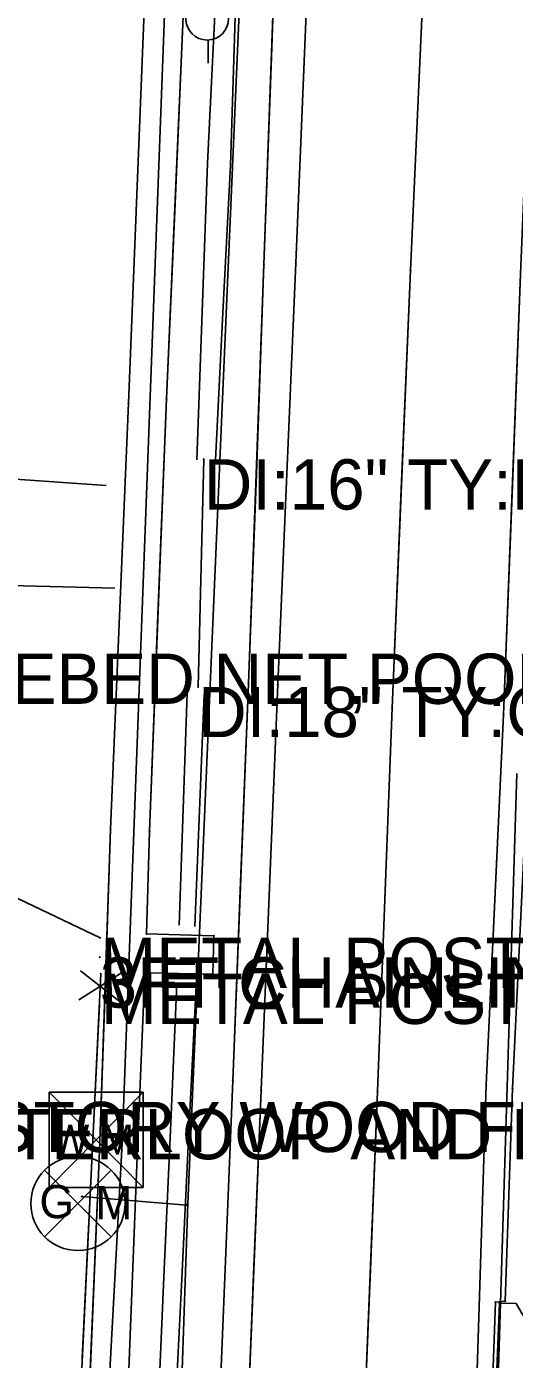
# Model space of a CAD drawing. Extents: x -99999 to 591807, y -99999 to 347168.
# Drawn here: x 591214 to 591262.4, y 320596.6 to 320729.1 of the extents above; entities that cross this region are included whole.
import ezdxf

# ---------------------------------------------------------------- set-up
doc = ezdxf.new("R2010")
doc.units = 0
for name, color, linetype in [('S_DITCHLINE', 7, 'Continuous'), ('S_DRG_PT_SYM', 7, 'Continuous'), ('S_DRIVEWAY', 7, 'Continuous'), ('S_EDGE_PAVEMENT', 7, 'Continuous'), ('S_FENCE', 7, 'Continuous'), ('S_FENCE_ANNOT', 7, 'Continuous'), ('S_GAS_UTILITIES', 7, 'Continuous'), ('S_GATE_ANNOT', 7, 'Continuous'), ('S_MISC_STRUCTURES_ANNOT', 7, 'Continuous'), ('S_MSC_PT_SYM', 7, 'Continuous'), ('S_PAVEMENT_CROWN', 7, 'Continuous'), ('S_RDW_PT_SYM', 7, 'Continuous'), ('S_SHOULDER', 7, 'Continuous'), ('S_SIDE_DRAIN', 7, 'Continuous'), ('S_SIDE_DRAIN_ANNOT', 7, 'Continuous'), ('S_SIDEWALK', 7, 'Continuous'), ('S_SURVEY_TEXT_ANNOT', 7, 'Continuous'), ('S_UTILITY_POLE', 7, 'Continuous'), ('S_UTL_PT_SYM', 7, 'Continuous'), ('S_WATER_UTILITIES', 7, 'Continuous')]:
    doc.layers.add(name, color=color, linetype=linetype)

msp = doc.modelspace()

# ---------------------------------------------------------------- linework, layer by layer
at = {"layer": 'S_DITCHLINE'}
for points in [[(591230.88, 320686.04), (591231.41, 320700.78), (591231.95, 320715.52), (591232.83, 320733.77)], [(591232.75, 320686), (591233.48, 320700.66), (591234.22, 320715.33), (591234.8, 320733.31)], [(591229.15, 320639.76), (591229.93, 320662.82)], [(591230.69, 320639.61), (591231.62, 320662.74)], [(591226.33, 320575.53), (591226.98, 320590.14), (591227.62, 320604.75), (591228.27, 320619.36), (591228.91, 320633.96)], [(591227.95, 320575.42), (591228.67, 320590), (591229.39, 320604.57), (591230.1, 320619.15), (591230.82, 320633.72)]]:
    msp.add_lwpolyline(points, dxfattribs=at)
at = {"layer": 'S_DRG_PT_SYM'}
for points in [[(591231.57, 320686.1), (591231.57, 320686.15), (591231.57, 320686.1), (591231.52, 320686.1), (591231.57, 320686.1), (591231.57, 320686.05), (591231.57, 320686.1), (591231.62, 320686.1)], [(591231.01, 320663.46), (591231.01, 320663.51), (591231.01, 320663.46), (591230.96, 320663.46), (591231.01, 320663.46), (591231.01, 320663.41), (591231.01, 320663.46), (591231.06, 320663.46)]]:
    msp.add_lwpolyline(points, dxfattribs=at)
at = {"layer": 'S_DRIVEWAY'}
for points in [[(591143.74, 320666.4), (591144.2, 320681.07), (591166.37, 320683.43), (591188.54, 320685.79), (591205.22, 320684.64), (591221.9, 320683.49)], [(591222.74, 320673.29), (591207.18, 320673.69), (591191.62, 320674.09), (591176.07, 320674.48), (591160.51, 320674.88), (591160.17, 320666.19)], [(591275.92, 320597.03), (591271.99, 320597.25), (591266.96, 320597.82), (591264.47, 320599.33), (591263.24, 320601.02), (591262.62, 320602.12), (591260.94, 320602.14), (591259.62, 320569.28)], [(591275.92, 320597.03), (591271.99, 320597.25), (591266.96, 320597.82), (591264.47, 320599.33), (591263.24, 320601.02), (591262.62, 320602.12), (591260.94, 320602.14), (591260.28, 320585.71), (591259.62, 320569.28)]]:
    msp.add_lwpolyline(points, dxfattribs=at)
at = {"layer": 'S_EDGE_PAVEMENT'}
for points in [[(591157.82, 321374.56), (591172, 321326.2), (591184.5, 321283.67), (591196.97, 321241.41), (591212.28, 321187.83), (591223.28, 321148.22), (591233.12, 321106.87), (591242.97, 321050.29), (591247.28, 321006.15), (591248.49, 320958.25), (591248.17, 320914.3), (591247.12, 320868.72), (591245.56, 320824.19), (591244.17, 320785.58), (591242.25, 320742.56), (591240.73, 320705.61), (591238.92, 320663.7), (591237.27, 320623.33), (591235.85, 320588.31), (591234.3, 320543.12), (591232.69, 320503.41), (591231.22, 320460.43), (591229.56, 320424.54)], [(591276.46, 321095.17), (591275.06, 321053.6), (591273.29, 321005.35), (591272, 320957.38), (591270.85, 320912.71), (591269.63, 320868.12), (591267.97, 320823.16), (591266.37, 320784.97), (591264.57, 320741.35), (591263.05, 320704.52), (591261.34, 320660.72), (591259.64, 320623.87), (591258.44, 320586.06), (591256.82, 320543.02), (591255.33, 320500.73), (591253.74, 320460.21), (591252.24, 320423.96)], [(591248.17, 320914.3), (591247.64, 320891.51), (591247.12, 320868.72), (591246.34, 320846.45), (591245.56, 320824.19), (591244.86, 320804.88), (591244.17, 320785.58), (591243.21, 320764.07), (591242.25, 320742.56), (591241.49, 320724.09), (591240.73, 320705.61), (591239.83, 320684.65), (591238.92, 320663.7), (591238.1, 320643.51), (591237.27, 320623.33), (591236.56, 320605.82), (591235.85, 320588.31)], [(591270.85, 320912.71), (591270.24, 320890.41), (591269.63, 320868.12), (591268.8, 320845.64), (591267.97, 320823.16), (591267.17, 320804.07), (591266.37, 320784.97), (591265.47, 320763.16), (591264.57, 320741.35), (591263.81, 320722.94), (591263.05, 320704.52), (591262.2, 320682.62), (591261.34, 320660.72), (591260.49, 320642.29), (591259.64, 320623.87), (591259.04, 320604.97), (591258.44, 320586.06)]]:
    msp.add_lwpolyline(points, dxfattribs=at)
at = {"layer": 'S_FENCE'}
for p, q in [((591221.28, 320638.51), (591161.96, 320666.77)), ((591218.49, 320575.55), (591221.35, 320634.93)), ((591219.18, 320632.34), (591223.41, 320635)), ((591223.27, 320632.14), (591219.32, 320635.2))]:
    msp.add_line(p, q, dxfattribs=at)
for points in [[(591221.28, 320638.51), (591203.69, 320646.89)], [(591219.51, 320596.68), (591221.21, 320631.91)]]:
    msp.add_lwpolyline(points, dxfattribs=at)
at = {"layer": 'S_GAS_UTILITIES'}
for p, q in [((591236.8, 320769.73), (591229.99, 320612.07)), ((591215.77, 320608.76), (591222.39, 320615.38)), ((591215.77, 320615.38), (591222.39, 320608.76)), ((591219.47, 320612.75), (591229.86, 320611.92)), ((591229.99, 320612.07), (591224.38, 320448.24))]:
    msp.add_line(p, q, dxfattribs=at)
msp.add_circle((591219.08, 320612.07), 4.68, dxfattribs=at)
at = {"layer": 'S_MSC_PT_SYM'}
for points in [[(591224.09, 320691.67), (591224.14, 320691.66), (591224.09, 320691.67), (591224.1, 320691.72), (591224.09, 320691.67), (591224.04, 320691.67), (591224.09, 320691.67), (591224.09, 320691.62)], [(591227.87, 320692.11), (591227.92, 320692.11), (591227.87, 320692.11), (591227.87, 320692.16), (591227.87, 320692.11), (591227.82, 320692.11), (591227.87, 320692.11), (591227.87, 320692.06)], [(591222.32, 320649.31), (591222.37, 320649.31), (591222.32, 320649.31), (591222.33, 320649.36), (591222.32, 320649.31), (591222.27, 320649.31), (591222.32, 320649.31), (591222.32, 320649.26)], [(591226.18, 320649.1), (591226.23, 320649.1), (591226.18, 320649.1), (591226.18, 320649.15), (591226.18, 320649.1), (591226.13, 320649.11), (591226.18, 320649.1), (591226.18, 320649.05)], [(591225.88, 320638.91), (591225.88, 320638.96), (591225.88, 320638.91), (591225.83, 320638.91), (591225.88, 320638.91), (591225.88, 320638.86), (591225.88, 320638.91), (591225.93, 320638.91)], [(591232.58, 320638.71), (591232.63, 320638.71), (591232.58, 320638.71), (591232.59, 320638.76), (591232.58, 320638.71), (591232.53, 320638.71), (591232.58, 320638.71), (591232.58, 320638.66)], [(591225.72, 320635.02), (591225.77, 320635.02), (591225.72, 320635.02), (591225.72, 320635.07), (591225.72, 320635.02), (591225.67, 320635.02), (591225.72, 320635.02), (591225.71, 320634.97)], [(591232.48, 320634.87), (591232.48, 320634.82), (591232.48, 320634.87), (591232.53, 320634.86), (591232.48, 320634.87), (591232.48, 320634.92), (591232.48, 320634.87), (591232.43, 320634.87)], [(591221.22, 320617.3), (591221.27, 320617.3), (591221.22, 320617.3), (591221.22, 320617.35), (591221.22, 320617.3), (591221.17, 320617.3), (591221.22, 320617.3), (591221.21, 320617.25)], [(591225.01, 320617.58), (591225.06, 320617.58), (591225.01, 320617.58), (591225.01, 320617.63), (591225.01, 320617.58), (591224.96, 320617.59), (591225.01, 320617.58), (591225.01, 320617.53)]]:
    msp.add_lwpolyline(points, close=True, dxfattribs=at)
for points in [[(591221.28, 320638.51), (591221.28, 320638.56), (591221.28, 320638.51), (591221.23, 320638.51), (591221.28, 320638.51), (591221.28, 320638.46), (591221.28, 320638.51), (591221.33, 320638.51)], [(591221.24, 320636.56), (591221.24, 320636.61), (591221.24, 320636.56), (591221.19, 320636.56), (591221.24, 320636.56), (591221.24, 320636.51), (591221.24, 320636.56), (591221.29, 320636.56)], [(591221.35, 320634.93), (591221.35, 320634.98), (591221.35, 320634.93), (591221.3, 320634.93), (591221.35, 320634.93), (591221.35, 320634.88), (591221.35, 320634.93), (591221.4, 320634.93)]]:
    msp.add_lwpolyline(points, dxfattribs=at)
at = {"layer": 'S_PAVEMENT_CROWN'}
for points in [[(591169.39, 321376.17), (591182.7, 321330.3), (591196.05, 321285.51), (591208.23, 321244.2), (591224.14, 321189.5), (591234.43, 321151.84), (591245.74, 321106.05), (591255.46, 321050.58), (591259.1, 321006.38), (591260.26, 320958.14), (591259.83, 320913.41), (591258.41, 320868.94), (591257.04, 320823.07), (591255.42, 320785.26), (591253.78, 320741.8), (591252.12, 320704.89), (591250.29, 320661.39), (591248.85, 320623.22), (591247.41, 320587.8), (591245.84, 320543.65), (591243.65, 320502.38), (591242.31, 320460.16), (591240.8, 320424.4)], [(591259.83, 320913.41), (591259.12, 320891.17), (591258.41, 320868.94), (591257.72, 320846), (591257.04, 320823.07), (591256.23, 320804.17), (591255.42, 320785.26), (591254.6, 320763.53), (591253.78, 320741.8), (591252.95, 320723.35), (591252.12, 320704.89), (591251.2, 320683.14), (591250.29, 320661.39), (591249.57, 320642.31), (591248.85, 320623.22), (591248.13, 320605.51), (591247.41, 320587.8)]]:
    msp.add_lwpolyline(points, dxfattribs=at)
at = {"layer": 'S_RDW_PT_SYM'}
for points in [[(591237.56, 320705.47), (591237.61, 320705.47), (591237.56, 320705.47), (591237.56, 320705.52), (591237.56, 320705.47), (591237.51, 320705.47), (591237.56, 320705.47), (591237.56, 320705.42)], [(591240.73, 320705.61), (591240.78, 320705.61), (591240.73, 320705.61), (591240.73, 320705.66), (591240.73, 320705.61), (591240.68, 320705.62), (591240.73, 320705.61), (591240.72, 320705.56)], [(591252.12, 320704.89), (591252.17, 320704.89), (591252.12, 320704.89), (591252.12, 320704.94), (591252.12, 320704.89), (591252.07, 320704.89), (591252.12, 320704.89), (591252.11, 320704.84)], [(591236.03, 320663.81), (591236.08, 320663.81), (591236.03, 320663.81), (591236.04, 320663.86), (591236.03, 320663.81), (591235.98, 320663.82), (591236.03, 320663.81), (591236.03, 320663.76)], [(591238.92, 320663.7), (591238.97, 320663.69), (591238.92, 320663.7), (591238.93, 320663.75), (591238.92, 320663.7), (591238.87, 320663.7), (591238.92, 320663.7), (591238.92, 320663.65)], [(591250.29, 320661.39), (591250.34, 320661.39), (591250.29, 320661.39), (591250.29, 320661.44), (591250.29, 320661.39), (591250.24, 320661.39), (591250.29, 320661.39), (591250.29, 320661.34)], [(591261.34, 320660.72), (591261.39, 320660.72), (591261.34, 320660.72), (591261.34, 320660.77), (591261.34, 320660.72), (591261.29, 320660.72), (591261.34, 320660.72), (591261.34, 320660.67)], [(591234.45, 320624.27), (591234.5, 320624.27), (591234.45, 320624.27), (591234.46, 320624.32), (591234.45, 320624.27), (591234.4, 320624.28), (591234.45, 320624.27), (591234.45, 320624.22)], [(591237.27, 320623.33), (591237.32, 320623.33), (591237.27, 320623.33), (591237.27, 320623.38), (591237.27, 320623.33), (591237.22, 320623.33), (591237.27, 320623.33), (591237.26, 320623.28)], [(591248.85, 320623.22), (591248.9, 320623.22), (591248.85, 320623.22), (591248.85, 320623.27), (591248.85, 320623.22), (591248.8, 320623.23), (591248.85, 320623.22), (591248.84, 320623.17)], [(591259.64, 320623.87), (591259.69, 320623.87), (591259.64, 320623.87), (591259.64, 320623.92), (591259.64, 320623.87), (591259.59, 320623.87), (591259.64, 320623.87), (591259.64, 320623.82)], [(591262.23, 320623.51), (591262.28, 320623.51), (591262.23, 320623.51), (591262.23, 320623.56), (591262.23, 320623.51), (591262.18, 320623.51), (591262.23, 320623.51), (591262.23, 320623.46)], [(591260.56, 320602.27), (591260.61, 320602.27), (591260.56, 320602.27), (591260.56, 320602.32), (591260.56, 320602.27), (591260.51, 320602.27), (591260.56, 320602.27), (591260.56, 320602.22)], [(591260.94, 320602.14), (591260.99, 320602.14), (591260.94, 320602.14), (591260.94, 320602.19), (591260.94, 320602.14), (591260.89, 320602.14), (591260.94, 320602.14), (591260.94, 320602.09)], [(591261.51, 320602.35), (591261.51, 320602.3), (591261.51, 320602.35), (591261.56, 320602.35), (591261.51, 320602.35), (591261.51, 320602.4), (591261.51, 320602.35), (591261.46, 320602.34)]]:
    msp.add_lwpolyline(points, close=True, dxfattribs=at)
at = {"layer": 'S_SHOULDER'}
for points in [[(591245.88, 320932.12), (591246.34, 320914.38), (591244.03, 320869.09), (591242.24, 320824.09), (591240.93, 320786.07), (591238.96, 320744.97), (591237.56, 320705.47), (591236.03, 320663.81), (591234.45, 320624.27), (591233.02, 320588.47), (591231.51, 320542.98), (591229.6, 320503.55), (591227.67, 320460.66), (591225.85, 320425.04)], [(591246.34, 320914.38), (591245.18, 320891.74), (591244.03, 320869.09), (591243.13, 320846.59), (591242.24, 320824.09), (591241.58, 320805.08), (591240.93, 320786.07), (591239.94, 320765.52), (591238.96, 320744.97), (591238.26, 320725.22), (591237.56, 320705.47), (591236.8, 320684.64), (591236.03, 320663.81), (591235.24, 320644.04), (591234.45, 320624.27), (591233.74, 320606.37), (591233.02, 320588.47)], [(591264.02, 320660.55), (591262.23, 320623.51), (591261.51, 320602.35), (591260.56, 320602.27), (591259.36, 320569.05), (591260.59, 320568.93), (591259.47, 320551.21), (591258.29, 320549.42)], [(591264.02, 320660.55), (591263.13, 320642.03), (591262.23, 320623.51), (591261.51, 320602.35), (591260.56, 320602.27), (591259.96, 320585.66), (591259.36, 320569.05), (591260.59, 320568.93), (591259.47, 320551.21), (591258.29, 320549.42)]]:
    msp.add_lwpolyline(points, dxfattribs=at)
at = {"layer": 'S_SIDE_DRAIN'}
msp.add_line((591231.57, 320686.1), (591231.01, 320663.46), dxfattribs=at)
at = {"layer": 'S_SIDEWALK'}
for points in [[(591237.48, 320924.93), (591235.93, 320886.27), (591235.81, 320878.8), (591241.84, 320878.47), (591241.64, 320874.69), (591235.54, 320874.77), (591234.43, 320851.97), (591232.89, 320820.68), (591232.43, 320805.82), (591231.9, 320788.12), (591239, 320787.63), (591238.84, 320783.73), (591231.61, 320784.03), (591230.57, 320756.55), (591229.51, 320729.43), (591227.87, 320692.11), (591226.18, 320649.1), (591225.88, 320638.91), (591232.58, 320638.71), (591232.48, 320634.87), (591225.72, 320635.02), (591225.01, 320617.58), (591223.33, 320575.28)], [(591219.91, 320876.07), (591231.73, 320875.49), (591230.68, 320851.86), (591229.67, 320820.62), (591229.01, 320806.94), (591228.34, 320790.52), (591228.05, 320787.96), (591226.65, 320756.32), (591225.61, 320729.85), (591224.09, 320691.67), (591222.32, 320649.31), (591221.22, 320617.3), (591219.52, 320576.85), (591217.68, 320534.67), (591217.86, 320536.9), (591216.22, 320501.63), (591214.62, 320467.91), (591200.76, 320468.74)], [(591219.91, 320876.07), (591231.73, 320875.49), (591230.68, 320851.86), (591230.17, 320836.24), (591229.67, 320820.62), (591229.01, 320806.94), (591228.34, 320790.52), (591228.05, 320787.96), (591227.35, 320772.14), (591226.65, 320756.32), (591226.13, 320743.09), (591225.61, 320729.85), (591224.85, 320710.76), (591224.09, 320691.67), (591223.21, 320670.49), (591222.32, 320649.31), (591221.77, 320633.31), (591221.22, 320617.3), (591220.37, 320597.07), (591219.52, 320576.85)], [(591229.51, 320729.43), (591228.69, 320710.77), (591227.87, 320692.11), (591227.03, 320670.61), (591226.18, 320649.1), (591225.88, 320638.91), (591232.58, 320638.71), (591232.48, 320634.87), (591225.72, 320635.02), (591225.01, 320617.58), (591224.17, 320596.43)]]:
    msp.add_lwpolyline(points, dxfattribs=at)
at = {"layer": 'S_UTILITY_POLE'}
msp.add_line((591232, 320725.49), (591232, 320727.81), dxfattribs=at)
msp.add_circle((591231.92, 320729.93), 2.13, dxfattribs=at)
at = {"layer": 'S_UTL_PT_SYM'}
for points in [[(591223.46, 320618.06), (591223.46, 320618.11), (591223.46, 320618.06), (591223.41, 320618.06), (591223.46, 320618.06), (591223.46, 320618.01), (591223.46, 320618.06), (591223.51, 320618.06)], [(591219.47, 320612.75), (591219.47, 320612.8), (591219.47, 320612.75), (591219.42, 320612.75), (591219.47, 320612.75), (591219.47, 320612.7), (591219.47, 320612.75), (591219.52, 320612.75)], [(591229.99, 320612.07), (591229.99, 320612.12), (591229.99, 320612.07), (591229.94, 320612.07), (591229.99, 320612.07), (591229.99, 320612.02), (591229.99, 320612.07), (591230.04, 320612.07)], [(591229.86, 320611.92), (591229.86, 320611.97), (591229.86, 320611.92), (591229.81, 320611.92), (591229.86, 320611.92), (591229.86, 320611.87), (591229.86, 320611.92), (591229.91, 320611.92)]]:
    msp.add_lwpolyline(points, dxfattribs=at)
at = {"layer": 'S_WATER_UTILITIES'}
for p, q in [((591228.85, 320761.64), (591223.46, 320618.06)), ((591262.69, 320654.85), (591256.28, 320448.6)), ((591216.21, 320623.15), (591225.55, 320623.15)), ((591216.21, 320623.15), (591216.21, 320613.66)), ((591216.21, 320623.15), (591225.55, 320613.66)), ((591225.55, 320623.15), (591216.21, 320613.66)), ((591225.55, 320623.15), (591225.55, 320613.66)), ((591223.46, 320618.06), (591214.3, 320448.45)), ((591216.21, 320613.66), (591225.55, 320613.66))]:
    msp.add_line(p, q, dxfattribs=at)

# ---------------------------------------------------------------- texts
at = {"layer": 'S_FENCE_ANNOT'}
for p in [(591161.96, 320661.77), (591221.28, 320633.51), (591221.35, 320629.93)]:
    msp.add_text('METAL POST WEBED NET,POOR', height=5, dxfattribs=at).set_placement(p)
at = {"layer": 'S_GAS_UTILITIES'}
for s, p in [('G', (591215.26, 320610.61)), ('M', (591220.82, 320610.5))]:
    msp.add_text(s, height=3.3, rotation=360, dxfattribs=at).set_placement(p)
at = {"layer": 'S_GATE_ANNOT'}
msp.add_text('3FT CHAINLINK GT', height=5, dxfattribs=at).set_placement((591221.24, 320631.56))
at = {"layer": 'S_MISC_STRUCTURES_ANNOT'}
msp.add_text('METERLOOP AND BE', height=5, dxfattribs=at).set_placement((591202.29, 320616.47))
at = {"layer": 'S_SIDE_DRAIN_ANNOT'}
for s, p in [('DI:16" TY:RCP CN:50% BTTM OF PI', (591231.57, 320681.1)), ('DI:18" TY:CMP CN:25% BTTM OF PI', (591231.01, 320658.46))]:
    msp.add_text(s, height=5, dxfattribs=at).set_placement(p)
at = {"layer": 'S_SURVEY_TEXT_ANNOT'}
msp.add_text('ONE STORY WOOD FRAME', height=5, dxfattribs=at).set_placement((591193.87, 320617.18))
at = {"layer": 'S_WATER_UTILITIES'}
msp.add_text('W M', height=3, rotation=360, dxfattribs=at).set_placement((591216.42, 320616.92))

doc.saveas('drawing.dxf')
